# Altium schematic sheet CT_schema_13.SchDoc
size 742 x 377 mm
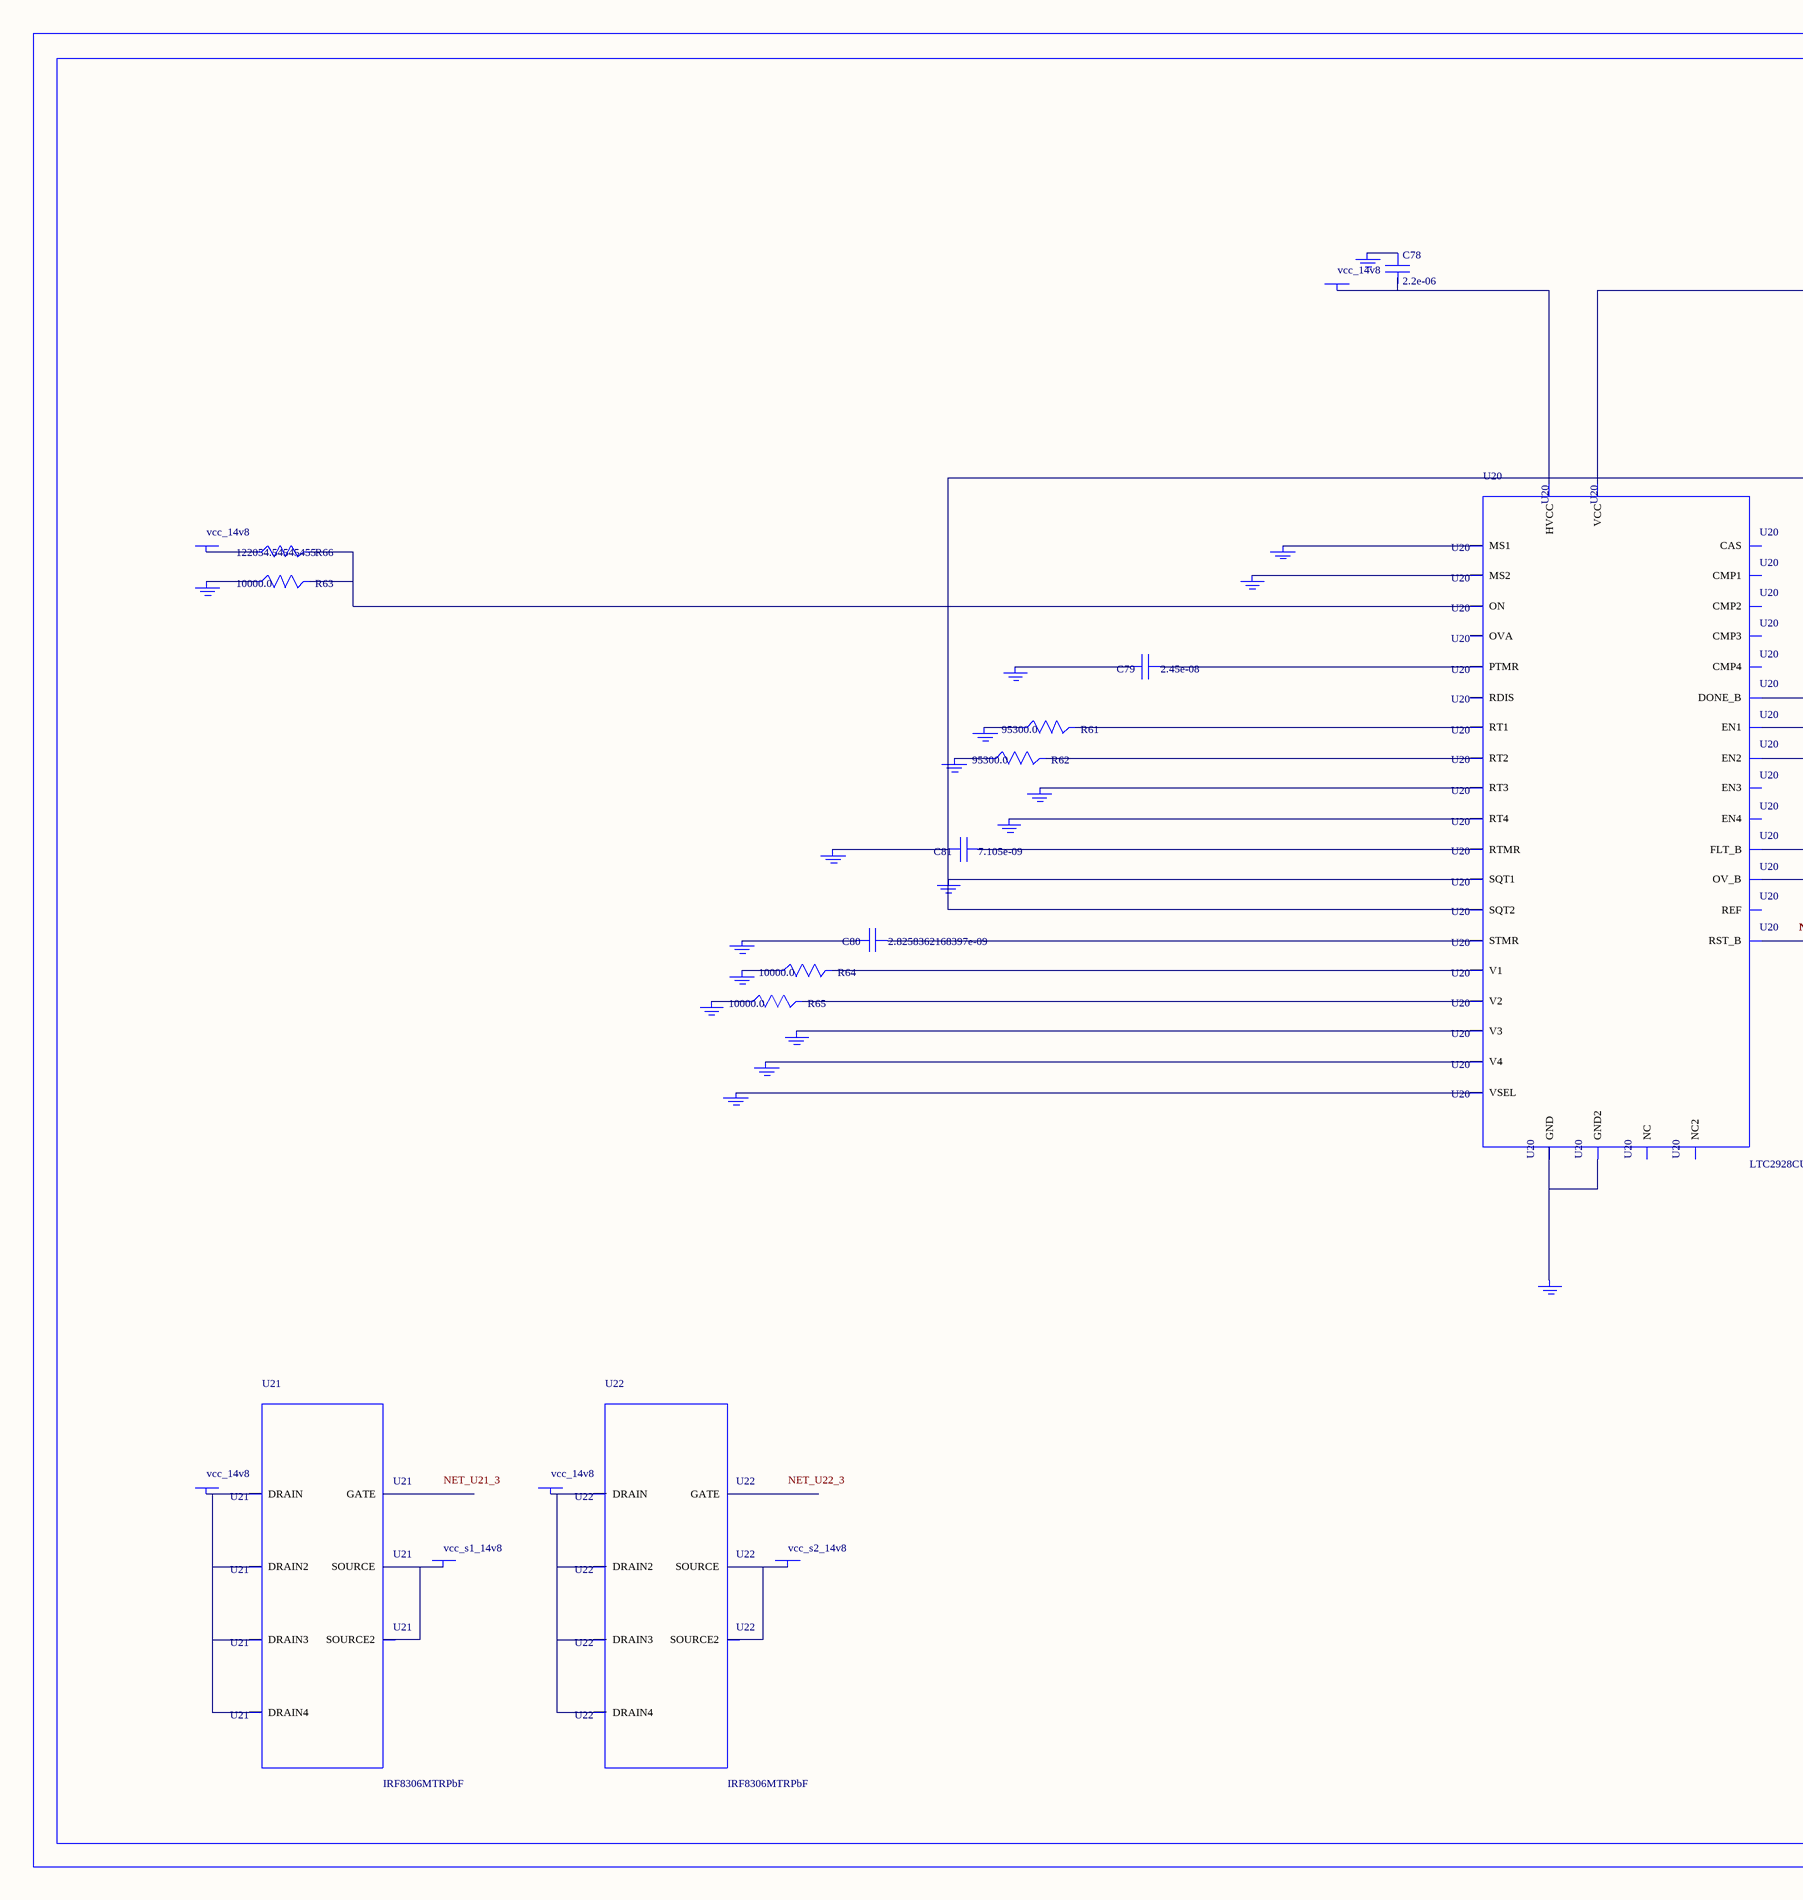
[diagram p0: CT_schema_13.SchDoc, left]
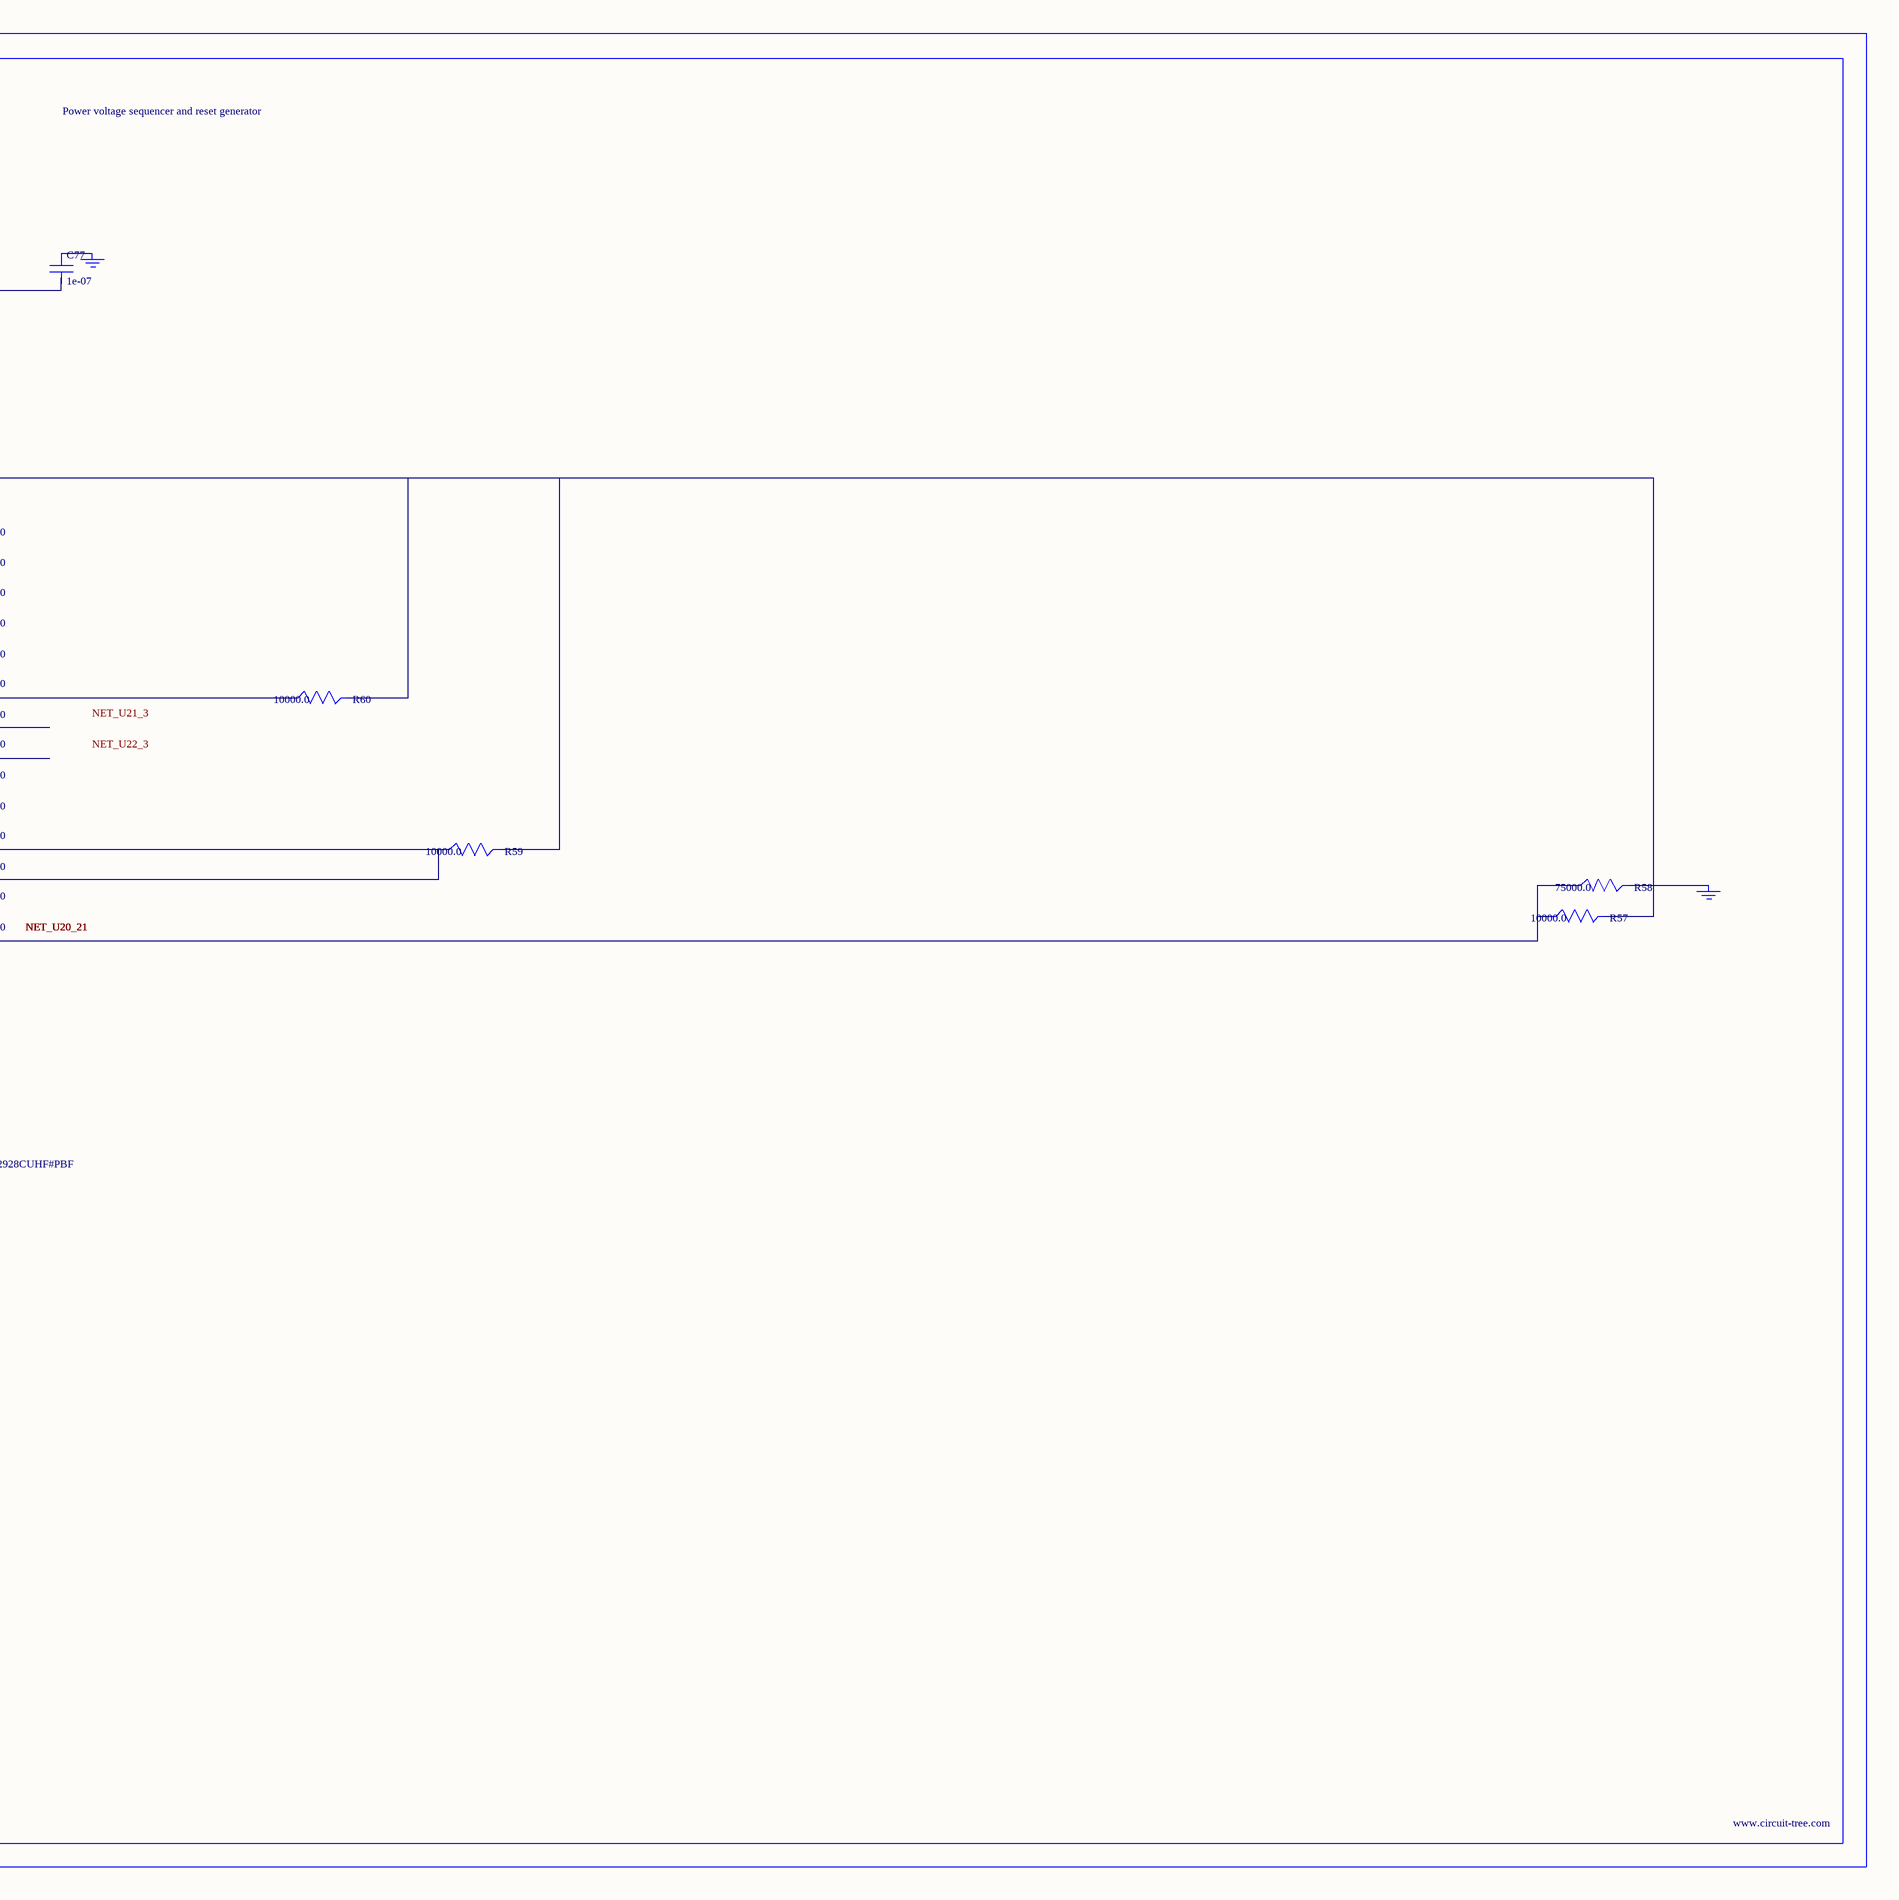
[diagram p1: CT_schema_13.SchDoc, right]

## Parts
BORDER12  (no value)
C77  1e-07  [C0402]
C78  2.2e-06  [C0603]
C79  2.45e-08  [R0603]
C80  2.8258362168397e-09  [R0603]
C81  7.105e-09  [R0603]
GND_INSTANCE_12_0  (no value)
GND_INSTANCE_12_1  (no value)
GND_INSTANCE_12_2  (no value)
GND_INSTANCE_12_3  (no value)
GND_INSTANCE_12_4  (no value)
GND_INSTANCE_12_5  (no value)
GND_INSTANCE_12_6  (no value)
GND_INSTANCE_12_7  (no value)
GND_INSTANCE_12_8  (no value)
GND_INSTANCE_12_9  (no value)
GND_INSTANCE_12_10  (no value)
GND_INSTANCE_12_11  (no value)
GND_INSTANCE_12_12  (no value)
GND_INSTANCE_12_13  (no value)
GND_INSTANCE_12_14  (no value)
GND_INSTANCE_12_15  (no value)
GND_INSTANCE_12_16  (no value)
GND_INSTANCE_12_17  (no value)
GND_INSTANCE_12_18  (no value)
GND_INSTANCE_12_19  (no value)
POWER_INSTANCE_12_0  vcc_14v8
POWER_INSTANCE_12_1  vcc_14v8
POWER_INSTANCE_12_2  vcc_14v8
POWER_INSTANCE_12_3  vcc_s1_14v8
POWER_INSTANCE_12_4  vcc_14v8
POWER_INSTANCE_12_5  vcc_s2_14v8
R57  10000.0  [R0603]
R58  75000.0  [R0603]
R59  10000.0  [R0603]
R60  10000.0  [R0603]
R61  95300.0  [R0603]
R62  95300.0  [R0603]
R63  10000.0  [R0603]
R64  10000.0  [R0603]
R65  10000.0  [R0603]
R66  122054.54545455  [R0603]
U20  LTC2928CUHF#PBF  [QFN-38_UHF]
U21  IRF8306MTRPbF  [IRF8306MTRPBF]
U22  IRF8306MTRPbF  [IRF8306MTRPBF]

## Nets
NetC77_1: C77.1 GND_INSTANCE_12_10.0(GND)
NetC77_2: C77.2 C81.2 GND_INSTANCE_12_5.0(GND) GND_INSTANCE_12_15.0(GND) R57.2 R59.2 R60.2 U20.10(SQT1) U20.11(SQT2) U20.22(VCC)
NetC78_1: C78.1 GND_INSTANCE_12_11.0(GND)
NetC78_2: C78.2 POWER_INSTANCE_12_1.0(PWR) U20.23(HVCC)
NetC79_1: C79.1 U20.27(PTMR)
NetC79_2: C79.2 GND_INSTANCE_12_14.0(GND)
NetC80_1: C80.1 U20.26(STMR)
NetC80_2: C80.2 GND_INSTANCE_12_13.0(GND)
NetC81_1: C81.1 U20.28(RTMR)
NetGND_INSTANCE_12_0_0: GND_INSTANCE_12_0.0(GND) R64.1
NetGND_INSTANCE_12_1_0: GND_INSTANCE_12_1.0(GND) R61.1
NetGND_INSTANCE_12_2_0: GND_INSTANCE_12_2.0(GND) R62.1
NetGND_INSTANCE_12_3_0: GND_INSTANCE_12_3.0(GND) U20.8(RT3)
NetGND_INSTANCE_12_4_0: GND_INSTANCE_12_4.0(GND) U20.9(RT4)
NetGND_INSTANCE_12_6_0: GND_INSTANCE_12_6.0(GND) U20.12(MS1)
NetGND_INSTANCE_12_7_0: GND_INSTANCE_12_7.0(GND) U20.13(MS2)
NetGND_INSTANCE_12_8_0: GND_INSTANCE_12_8.0(GND) R63.1
NetGND_INSTANCE_12_9_0: GND_INSTANCE_12_9.0(GND) R58.2
NetGND_INSTANCE_12_12_0: GND_INSTANCE_12_12.0(GND) U20.25(VSEL)
NetGND_INSTANCE_12_16_0: GND_INSTANCE_12_16.0(GND) U20.30(V4)
NetGND_INSTANCE_12_17_0: GND_INSTANCE_12_17.0(GND) U20.32(V3)
NetGND_INSTANCE_12_18_0: GND_INSTANCE_12_18.0(GND) R65.1
NetGND_INSTANCE_12_19_0: GND_INSTANCE_12_19.0(GND) U20.24(GND) U20.39(GND2)
NetPOWER_INSTANCE_12_0_0: POWER_INSTANCE_12_0.0(PWR) R66.1
NetPOWER_INSTANCE_12_2_0: POWER_INSTANCE_12_2.0(PWR) U21.1(DRAIN) U21.2(DRAIN2) U21.6(DRAIN3) U21.7(DRAIN4)
NetPOWER_INSTANCE_12_3_0: POWER_INSTANCE_12_3.0(PWR) U21.4(SOURCE) U21.5(SOURCE2)
NetPOWER_INSTANCE_12_4_0: POWER_INSTANCE_12_4.0(PWR) U22.1(DRAIN) U22.2(DRAIN2) U22.6(DRAIN3) U22.7(DRAIN4)
NetPOWER_INSTANCE_12_5_0: POWER_INSTANCE_12_5.0(PWR) U22.4(SOURCE) U22.5(SOURCE2)
NetR57_1: R57.1 R58.1 U20.21(RST_B)
NetR59_1: R59.1 U20.19(FLT_B) U20.20(OV_B)
NetR60_1: R60.1 U20.18(DONE_B)
NetR61_2: R61.2 U20.6(RT1)
NetR62_2: R62.2 U20.7(RT2)
NetR63_2: R63.2 R66.2 U20.16(ON)
NetR64_2: R64.2 U20.3(V1)
NetR65_2: R65.2 U20.38(V2)

Not connected (* = marked no-connect by the designer): U20 1(OVA) 2(EN1) 4(NC) 5(REF) 14(RDIS) 15(CAS) 17(NC2) 29(EN4) 31(EN3) 33(CMP3) 34(CMP4) 35(CMP1) 36(CMP2) 37(EN2); U21 3(GATE); U22 3(GATE)

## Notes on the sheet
- Labels drawn without touching a wire or pin: NET_U21_3, NET_U22_3

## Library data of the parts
BORDER12 = BORDER_PAGE12
C77 = C0402C104K3RACTU
C78 = GRM188R61H225KE1115D
C79 = C79
C80 = C80
C81 = C81
GND_INSTANCE_12_0-GND_INSTANCE_12_19 = GND
POWER_INSTANCE_12_0-POWER_INSTANCE_12_5 = PWR
R57 R59 R60 R63-R65 = RC0603JR-0710KL
R58 = RC0603JR-0775KL
R61 R62 = RC0603FR-0795K3L
R66 = R66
